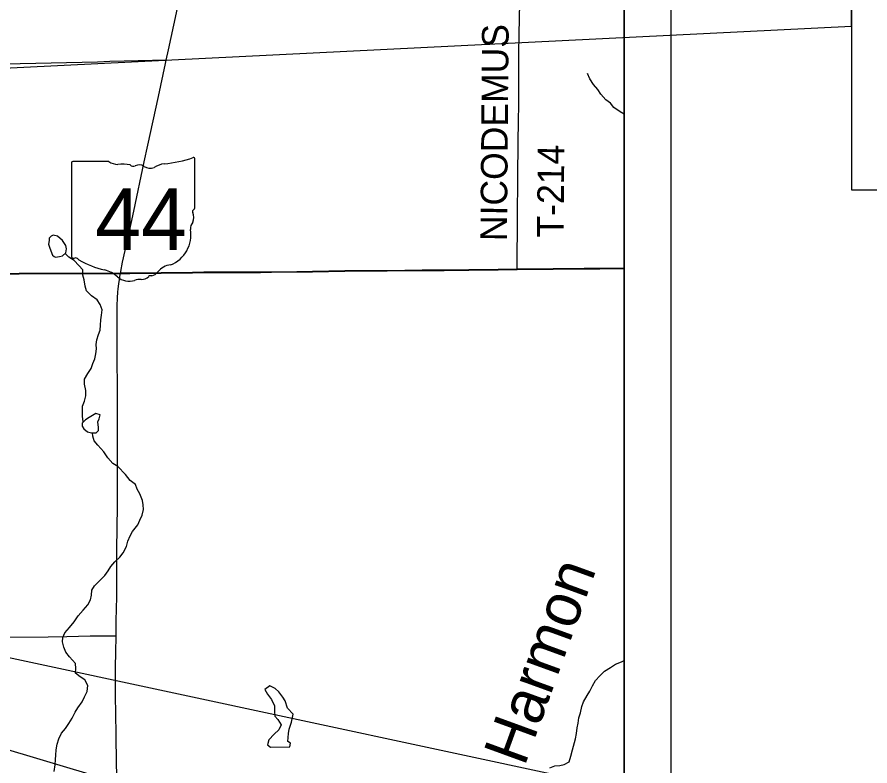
# Model space of a CAD drawing. Extents: x 0 to 34, y 0 to 22.
# Drawn here: x 7.601 to 9.426, y 16.463 to 18.065 of the extents above; entities that cross this region are included whole.
import ezdxf

# ---------------------------------------------------------------- set-up
doc = ezdxf.new("R2010")
doc.units = 0
for name, color, linetype in [('GM_X_Corporation', 7, 'Continuous'), ('GM_X_County_Road', 7, 'Continuous'), ('GM_X_Minor_Lake', 7, 'Continuous'), ('GM_X_Minor_River', 7, 'Continuous'), ('GM_X_Minor_River_Text', 7, 'Continuous'), ('GM_X_State_Location', 7, 'Continuous'), ('GM_X_State_Route', 7, 'Continuous'), ('GM_X_State_Shield', 7, 'Continuous'), ('GM_X_Township_Road', 7, 'Continuous'), ('GM_X_Township_Road_Text', 7, 'Continuous'), ('SH_Data', 7, 'Continuous'), ('SH_Text', 7, 'Continuous')]:
    doc.layers.add(name, color=color, linetype=linetype)

msp = doc.modelspace()

# ---------------------------------------------------------------- linework, layer by layer
at = {"layer": 'GM_X_Corporation'}
for points in [[(7.5349, 17.5157), (7.6058, 17.5164), (7.6642, 17.5169), (7.8222, 17.5175), (7.8425, 17.5175), (7.9768, 17.5188), (8.001, 17.5192), (8.0277, 17.5197), (8.1223, 17.5196), (8.1456, 17.5198), (8.1998, 17.5204), (8.2334, 17.5209), (8.3023, 17.522), (8.3931, 17.5227), (8.4683, 17.5236), (8.5149, 17.524), (8.5677, 17.5246), (8.6305, 17.5253), (8.6711, 17.5259), (8.6833, 17.5261), (8.748, 17.5267), (8.8145, 17.5272), (8.8481, 17.5273), (8.9, 17.5277), (8.9, 20.9)], [(8.9, 14.1), (8.9, 17.5277), (8.8481, 17.5273), (8.8145, 17.5272), (8.748, 17.5267), (8.6833, 17.5261), (8.6711, 17.5259), (8.6305, 17.5253), (8.5677, 17.5246), (8.5149, 17.524), (8.4683, 17.5236), (8.3931, 17.5227), (8.3023, 17.522), (8.2334, 17.5209), (8.1998, 17.5204), (8.1456, 17.5198), (8.1223, 17.5196), (8.0277, 17.5197), (8.001, 17.5192), (7.9768, 17.5188), (7.8425, 17.5175), (7.8222, 17.5175), (7.6642, 17.5169), (7.6058, 17.5164), (7.5349, 17.5157)]]:
    msp.add_lwpolyline(points, dxfattribs=at)
at = {"layer": 'GM_X_County_Road'}
for points in [[(7.024, 17.5117), (7.0506, 17.5119), (7.076, 17.5119), (7.0983, 17.512), (7.1244, 17.512), (7.1455, 17.5122), (7.2909, 17.5132), (7.3425, 17.5134), (7.368, 17.5136), (7.5351, 17.5151), (7.606, 17.5158), (7.6644, 17.5163), (7.8224, 17.5169)], [(7.8224, 17.5169), (7.8427, 17.517), (7.977, 17.5183), (8.0012, 17.5187), (8.0279, 17.5191), (8.1225, 17.519), (8.1458, 17.5192), (8.2, 17.5199), (8.2336, 17.5204), (8.3025, 17.5214), (8.3933, 17.5221), (8.4685, 17.5231), (8.5151, 17.5234), (8.5679, 17.5241), (8.6307, 17.5248), (8.6713, 17.5254)], [(8.6713, 17.5254), (8.6835, 17.5256), (8.7482, 17.5262), (8.8147, 17.5266), (8.8483, 17.5267), (8.9, 17.5271)]]:
    msp.add_lwpolyline(points, dxfattribs=at)
at = {"layer": 'GM_X_Minor_Lake'}
for p, q in [((7.6709, 17.5727), (7.6759, 17.5595)), ((7.7556, 17.2084), (7.7481, 17.2038)), ((8.1435, 16.5035), (8.1852, 16.5036))]:
    msp.add_line(p, q, dxfattribs=at)
for points in [[(7.6759, 17.5595), (7.6775, 17.5557), (7.6806, 17.5527), (7.684, 17.5516), (7.6919, 17.5532), (7.6987, 17.5544), (7.7058, 17.5606), (7.7073, 17.5693), (7.7057, 17.5769), (7.6983, 17.5871), (7.6876, 17.5964), (7.6785, 17.599), (7.6744, 17.5967), (7.6703, 17.5924), (7.6699, 17.5875), (7.6689, 17.5795), (7.6709, 17.5727)], [(7.7481, 17.2038), (7.7406, 17.1965), (7.7407, 17.1897), (7.7442, 17.184), (7.7522, 17.178), (7.7609, 17.1755), (7.7704, 17.176), (7.7753, 17.1806), (7.7759, 17.1874), (7.7743, 17.1992), (7.7772, 17.206), (7.7791, 17.214), (7.7699, 17.217), (7.7628, 17.2127), (7.7556, 17.2084)], [(8.1852, 16.5036), (8.1862, 16.5116), (8.1809, 16.5157), (8.1815, 16.524), (8.1822, 16.5324), (8.1836, 16.5419), (8.1884, 16.5568), (8.1923, 16.5739), (8.1801, 16.5867), (8.1746, 16.6025), (8.1696, 16.6104), (8.1615, 16.6214), (8.1535, 16.6285), (8.1424, 16.6344), (8.1311, 16.6267), (8.1369, 16.6169), (8.1454, 16.6049), (8.1524, 16.5913), (8.1521, 16.5795), (8.153, 16.5693), (8.1595, 16.5621), (8.1665, 16.5508), (8.1617, 16.5405), (8.1512, 16.5313), (8.1399, 16.519), (8.137, 16.508), (8.1435, 16.5035)]]:
    msp.add_lwpolyline(points, dxfattribs=at)
at = {"layer": 'GM_X_Minor_River'}
for points in [[(8.9, 17.8578), (8.8917, 17.8623), (8.8783, 17.8716), (8.8707, 17.8814), (8.8607, 17.8881), (8.8504, 17.9005), (8.8434, 17.9103), (8.8346, 17.9212), (8.8269, 17.9329), (8.8218, 17.9446), (8.8222, 17.9438)], [(7.7431, 17.199), (7.7416, 17.2113), (7.7417, 17.233), (7.7454, 17.2436), (7.7483, 17.2547), (7.7485, 17.2661), (7.7454, 17.2797), (7.7456, 17.2907), (7.7527, 17.3026), (7.7597, 17.3137), (7.7634, 17.3243), (7.7678, 17.3343), (7.7696, 17.3445), (7.7714, 17.3552), (7.7709, 17.3647), (7.7719, 17.3749), (7.7756, 17.386), (7.7789, 17.3955), (7.7799, 17.4058), (7.7805, 17.4172), (7.7819, 17.4278), (7.7837, 17.4388), (7.7794, 17.4506), (7.7725, 17.4604), (7.761, 17.469), (7.7499, 17.4798), (7.7468, 17.4897), (7.7451, 17.5029), (7.742, 17.5132), (7.7422, 17.5242), (7.7338, 17.5339), (7.7238, 17.5448), (7.7124, 17.5519), (7.7046, 17.5595)], [(7.6806, 16.4514), (7.6827, 16.4655), (7.6837, 16.4769), (7.6847, 16.4864), (7.6853, 16.4974), (7.6875, 16.5095), (7.6907, 16.521), (7.6967, 16.5332), (7.7049, 16.5432), (7.7123, 16.5535), (7.7194, 16.5653), (7.7257, 16.5779), (7.7313, 16.5875), (7.7406, 16.6001), (7.7458, 16.6108), (7.7517, 16.6226), (7.7527, 16.6352), (7.7461, 16.6473), (7.7362, 16.6536), (7.7266, 16.6618), (7.7269, 16.6717), (7.7264, 16.6823), (7.7137, 16.6962), (7.7057, 16.7068), (7.7014, 16.7173), (7.6986, 16.7283), (7.6992, 16.7382), (7.7033, 16.7481), (7.7138, 16.7589), (7.7239, 16.7715), (7.732, 16.7845), (7.7425, 16.7964), (7.7526, 16.8075), (7.7585, 16.8186), (7.7607, 16.8285), (7.7617, 16.8388), (7.7673, 16.8483), (7.7793, 16.8602), (7.789, 16.8702), (7.7965, 16.8802), (7.8017, 16.8901), (7.8106, 16.9001), (7.8215, 16.9097), (7.8286, 16.9193), (7.8353, 16.9326), (7.8385, 16.9437), (7.8433, 16.9551), (7.8482, 16.9647), (7.8597, 16.9788), (7.8642, 16.9888), (7.8693, 16.9998), (7.8722, 17.0116), (7.871, 17.0215), (7.8701, 17.0313), (7.8639, 17.0449), (7.8581, 17.0555), (7.855, 17.0653), (7.8435, 17.0739), (7.8331, 17.0867), (7.8167, 17.1036), (7.806, 17.1099), (7.7956, 17.122), (7.7868, 17.1352), (7.7741, 17.1491), (7.7664, 17.1588), (7.7637, 17.1687), (7.7629, 17.1756)], [(8.7409, 16.4592), (8.7519, 16.4631), (8.7621, 16.464), (8.7719, 16.4664), (8.7824, 16.4718), (8.7857, 16.484), (8.7897, 16.4974), (8.7963, 16.521), (8.798, 16.5328), (8.7994, 16.5449), (8.8016, 16.5548), (8.8033, 16.5659), (8.8066, 16.5769), (8.8095, 16.5902), (8.8128, 16.6001), (8.8206, 16.6135), (8.8265, 16.6231), (8.8325, 16.6345), (8.8388, 16.646), (8.8481, 16.6556), (8.8582, 16.6656), (8.871, 16.6737), (8.8816, 16.6806), (8.894, 16.6861), (8.9, 16.6889)]]:
    msp.add_lwpolyline(points, dxfattribs=at)
at = {"layer": 'GM_X_State_Route'}
for points in [[(7.8224, 17.5169), (7.8233, 17.5212), (7.8272, 17.5407), (7.8396, 17.5971), (7.8512, 17.6499), (7.8736, 17.7557), (7.8813, 17.7909), (7.9037, 17.8955), (7.9188, 17.966), (7.9205, 17.9733), (7.9254, 17.9951), (7.9369, 18.048), (7.9553, 18.1349)], [(7.8147, 16.4448), (7.8143, 16.4683), (7.8141, 16.4888), (7.8137, 16.5093), (7.8134, 16.5316), (7.8121, 16.6143), (7.812, 16.6485), (7.8123, 16.6752), (7.8129, 16.7056), (7.8133, 16.7415), (7.8137, 16.7735), (7.8145, 16.8246), (7.8151, 16.9124), (7.8159, 16.9858), (7.8162, 17.0053), (7.8163, 17.0152), (7.8165, 17.0804), (7.8163, 17.1456), (7.8163, 17.2247), (7.8162, 17.2466), (7.8162, 17.2555), (7.8162, 17.2623), (7.8161, 17.2875), (7.8159, 17.3179), (7.8157, 17.446), (7.8158, 17.4511), (7.8158, 17.4538), (7.816, 17.458), (7.8165, 17.4682), (7.8167, 17.4732), (7.8169, 17.4766), (7.8175, 17.484), (7.8188, 17.4946), (7.8202, 17.5039), (7.8219, 17.5143), (7.8224, 17.5169)]]:
    msp.add_lwpolyline(points, dxfattribs=at)
at = {"layer": 'GM_X_State_Shield'}
for p, q in [((7.718, 17.7531), (7.718, 17.553)), ((7.7979, 17.7565), (7.7206, 17.7565)), ((7.9817, 17.6568), (7.9817, 17.7615)), ((7.9817, 17.6568), (7.9817, 17.6568))]:
    msp.add_line(p, q, dxfattribs=at)
for centre, radius, start, end in [((7.7211, 17.7535), 0.00305, 98.1301, 188.1301), ((7.8162, 17.7797), 0.0296, 231.6195, 271.1119), ((7.9235, 17.6954), 0.0563, 97.3462, 120.7689), ((7.8878, 18.0293), 0.2796, 275.8445, 288.9065), ((7.9788, 17.7619), 0.00294, 351.8621, 97.738), ((7.8261, 17.6442), 0.1064, 80.4867, 94.9883), ((7.8502, 17.7545), 0.00855, 219.7921, 297.1024), ((7.8628, 17.7314), 0.0178, 54.4667, 119.1411), ((7.8857, 17.7631), 0.0214, 233.8562, 294.8282), ((7.981, 17.6491), 0.00454, 107.944, 210.337), ((7.9521, 17.6359), 0.0273, 340.033, 23.6496), ((7.9786, 17.6564), 0.00314, 289.6038, 7.7341), ((7.9922, 17.613), 0.0198, 136.8065, 186.9296), ((7.9035, 17.5997), 0.0699, 292.3089, 8.9858), ((7.7211, 17.5525), 0.00308, 171.9584, 258.3066), ((7.7216, 17.573), 0.0235, 267.339, 280.6039), ((7.7264, 17.5414), 0.00848, 29.7484, 93.2717), ((7.8334, 17.7212), 0.2019, 240.4129, 257.1985), ((7.9329, 17.4968), 0.0383, 94.4031, 142.5768), ((7.7732, 17.463), 0.0632, 47.1842, 75.836), ((7.8844, 17.5336), 0.0226, 282.8732, 323.2771), ((7.8416, 17.5404), 0.0401, 230.7004, 286.2918), ((7.8647, 17.4712), 0.0329, 85.6951, 111.2099), ((7.8677, 17.5254), 0.0214, 268.777, 315.5493), ((7.887, 17.506), 0.00601, 65.7517, 132.6484)]:
    msp.add_arc(centre, radius, start, end, dxfattribs=at)
at = {"layer": 'GM_X_Township_Road'}
for points in [[(8.6713, 17.5254), (8.6713, 17.5322), (8.6713, 17.5718), (8.6717, 17.5948), (8.6718, 17.6109), (8.6719, 17.6258), (8.6718, 17.6513), (8.6725, 17.7073), (8.6725, 17.7253), (8.6728, 17.7439), (8.6732, 17.7762), (8.6734, 17.7986), (8.6741, 17.8421), (8.6745, 17.8788), (8.6748, 17.9067), (8.6748, 17.9279), (8.6746, 17.9565), (8.6749, 17.9875), (8.6757, 18.0285), (8.6768, 18.0957)], [(7.5755, 17.9649), (7.7732, 17.9697), (7.8, 17.9706), (7.8908, 17.973), (7.9205, 17.9733)], [(6.9708, 16.7354), (7.0228, 16.736), (7.0806, 16.7362), (7.1353, 16.7365), (7.2086, 16.7373), (7.2731, 16.7373), (7.2894, 16.7373), (7.3441, 16.7374), (7.3732, 16.7379), (7.3937, 16.738), (7.4148, 16.7381), (7.5134, 16.7386), (7.5592, 16.7384), (7.6678, 16.7394), (7.7076, 16.7399), (7.7579, 16.7412), (7.7776, 16.7413), (7.7909, 16.7415), (7.8133, 16.7415)]]:
    msp.add_lwpolyline(points, dxfattribs=at)
at = {"layer": 'SH_Data'}
for p, q in [((9, 21), (9, 14)), ((8.9, 20.9), (8.9, 14.1))]:
    msp.add_line(p, q, dxfattribs=at)
at = {"layer": 'SH_Text'}
for points in [[(9.3865, 18.3957), (4.9237, 17.8249), (9.3865, 18.0457)], [(9.3865, 17.6957), (11.1242, 17.6957), (11.1242, 18.3957), (9.3865, 18.3957)], [(9.3865, 16.3077), (5.2632, 17.1919), (9.3865, 15.9577)]]:
    msp.add_lwpolyline(points, close=True, dxfattribs=at)

# ---------------------------------------------------------------- texts
at = {"layer": 'GM_X_Minor_River_Text'}
msp.add_text('Harmon', height=0.09471, rotation=69.9863, dxfattribs=at).set_placement((8.6868, 16.4602))
at = {"layer": 'GM_X_State_Location'}
msp.add_text('44', height=0.000189, rotation=0, dxfattribs=at).set_placement((7.7992, 17.6259))
for s in ['s', 'r']:
    msp.add_text(s, height=0.000189, dxfattribs=at).set_placement((7.8469, 17.6397))
at = {"layer": 'GM_X_State_Shield'}
msp.add_text('44', height=0.13184, dxfattribs=at).set_placement((7.7686, 17.5671))
at = {"layer": 'GM_X_Township_Road_Text'}
for s, rotation, p in [('NICODEMUS', 89.5401, (8.6493, 17.5858)), ('T-214', 89.4555, (8.7703, 17.5934))]:
    msp.add_text(s, height=0.05682, rotation=rotation, dxfattribs=at).set_placement(p)

doc.saveas('drawing.dxf')
